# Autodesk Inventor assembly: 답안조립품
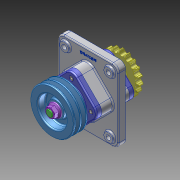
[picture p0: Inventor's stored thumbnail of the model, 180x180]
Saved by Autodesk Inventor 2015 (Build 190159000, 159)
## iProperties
Created: 2026-07
Part Number: 답안조립품
Document SubType Name: Assembly
Designer: user
Author: user
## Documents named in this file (12)
- C:\Users\user\Desktop\760705V1010\답안조립품.iam
- C:\Users\user\Desktop\760705V1010\본체.ipt
- C:\Users\user\Desktop\760705V1010\가져온 구성요소\6각 구멍붙이 볼트 M6x16\6각 구멍붙이 볼트 M6x16.ipt
- C:\Users\user\Desktop\760705V1010\가져온 구성요소\6각 플랜지 너트 M16\6각 플랜지 너트 M16.ipt
- C:\Users\user\Desktop\760705V1010\가져온 구성요소\V-벨트풀리\V-벨트풀리.ipt
- C:\Users\user\Desktop\760705V1010\가져온 구성요소\깊은 홈 볼 베어링 6206\깊은 홈 볼 베어링 6206.ipt
- C:\Users\user\Desktop\760705V1010\가져온 구성요소\오일 실 30 45 8\오일 실 30 45 8.ipt
- C:\Users\user\Desktop\760705V1010\가져온 구성요소\체인 스프로킷\체인 스프로킷.ipt
- C:\Users\user\Desktop\760705V1010\가져온 구성요소\축\축.ipt
- C:\Users\user\Desktop\760705V1010\가져온 구성요소\칼라\칼라.ipt
- C:\Users\user\Desktop\760705V1010\가져온 구성요소\커버\커버.ipt
- C:\Users\user\Desktop\760705V1010\가져온 구성요소\평행 키 6x6x20\평행 키 6x6x20.ipt
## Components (11 placed, 3 different names)
1. 6각 구멍붙이 볼트 M6x16:1
2. 6각 플랜지 너트 M16:1
3. V-벨트풀리:1
4. 6각 플랜지 너트 M16:2
5. 6각 구멍붙이 볼트 M6x16:2
6. 6각 구멍붙이 볼트 M6x16:3
7. 6각 구멍붙이 볼트 M6x16:4
8. 6각 구멍붙이 볼트 M6x16:5
9. 6각 구멍붙이 볼트 M6x16:6
10. 6각 구멍붙이 볼트 M6x16:7
11. 6각 구멍붙이 볼트 M6x16:8
